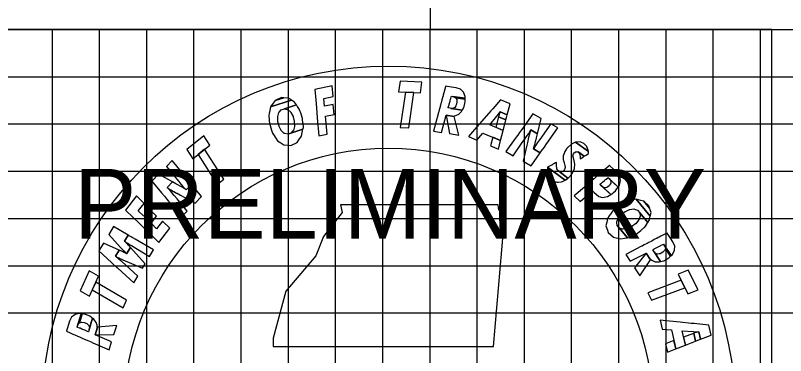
# Model space of a CAD drawing. Extents: x -10 to 342, y -5 to 215.
# Drawn here: x 313.22 to 329.53, y 195.1 to 202.3 of the extents above; entities that cross this region are included whole.
import ezdxf

# ---------------------------------------------------------------- set-up
doc = ezdxf.new("R2010")
doc.units = 0
for name, color, linetype in [('SHEET_LOGO', 7, 'Continuous'), ('SHEET_PRELIM', 7, 'Continuous'), ('SHEET_PROJ_NUMBER', 7, 'Continuous'), ('XS_SHEET_MAJOR_GRIDS', 7, 'Continuous'), ('XS_SHEET_MEDIUM_GRIDS', 7, 'Continuous'), ('XS_SHEET_MINOR_GRIDS', 7, 'Continuous')]:
    doc.layers.add(name, color=color, linetype=linetype)

msp = doc.modelspace()

# ---------------------------------------------------------------- linework, layer by layer
at = {"layer": 'SHEET_LOGO'}
for points in [[(313, 185.757), (329.243, 185.757), (329.243, 202), (313, 202)], [(321.366, 200.903), (321.333, 200.676), (321.797, 200.658), (321.83, 200.885)], [(319.612, 200.131), (319.648, 199.748), (319.82, 199.783), (319.784, 200.165), (319.971, 200.203), (319.952, 200.414), (319.765, 200.376), (319.75, 200.538), (319.95, 200.579), (319.929, 200.804), (319.557, 200.729), (319.578, 200.504), (319.593, 200.342)], [(322.172, 200.213), (322.075, 199.849), (322.247, 199.822), (322.345, 200.185), (322.515, 200.158), (322.512, 200.171), (322.55, 200.178), (322.609, 200.204), (322.67, 200.265), (322.684, 200.291), (322.386, 200.338), (322.388, 200.345), (322.395, 200.371), (322.404, 200.405), (322.408, 200.42), (322.424, 200.48), (322.424, 200.48), (322.436, 200.524), (322.436, 200.524), (322.439, 200.535), (322.449, 200.57), (322.453, 200.586), (322.453, 200.588), (322.743, 200.542), (322.742, 200.584), (322.708, 200.673), (322.644, 200.734), (322.551, 200.765), (322.455, 200.78), (322.331, 200.8), (322.33, 200.8), (322.326, 200.785), (322.313, 200.735), (322.291, 200.655), (322.281, 200.616), (322.28, 200.613), (322.276, 200.598), (322.267, 200.563), (322.264, 200.552), (322.252, 200.508), (322.236, 200.448), (322.231, 200.432), (322.222, 200.399), (322.215, 200.373), (322.213, 200.365), (322.206, 200.339), (322.188, 200.271), (322.179, 200.237), (322.176, 200.225)], [(318.681, 200.44), (318.624, 200.36), (319.064, 200.505), (319.002, 200.546), (318.902, 200.554), (318.719, 200.494)], [(318.853, 200.558), (318.719, 200.494), (318.902, 200.554), (318.854, 200.558)], [(321.48, 200.67), (321.371, 199.923), (321.548, 199.916), (321.656, 200.664)], [(322.485, 200.33), (322.44, 200.329), (322.684, 200.291), (322.687, 200.298), (322.701, 200.323), (322.718, 200.355), (322.721, 200.371), (322.735, 200.431), (322.744, 200.475), (322.744, 200.487), (322.743, 200.524), (322.549, 200.555), (322.567, 200.515), (322.567, 200.503), (322.569, 200.458), (322.553, 200.397), (322.544, 200.383), (322.524, 200.351)], [(322.512, 200.576), (322.549, 200.555), (322.743, 200.524), (322.743, 200.54), (322.743, 200.542), (322.479, 200.584)], [(319.003, 199.55), (319.051, 199.547), (319.185, 199.61), (319.222, 199.662), (319.28, 199.744), (319.295, 199.818), (319.309, 199.886), (318.988, 199.781), (318.987, 199.781), (318.924, 199.796), (318.916, 199.798), (318.914, 199.8), (318.852, 199.857), (318.851, 199.859), (318.849, 199.863), (318.804, 199.946), (318.803, 199.95), (318.802, 199.955), (318.778, 200.043), (318.776, 200.048), (318.776, 200.053), (318.773, 200.149), (318.774, 200.153), (318.774, 200.155), (318.796, 200.239), (318.796, 200.24), (318.804, 200.25), (318.847, 200.301), (318.915, 200.323), (319.169, 200.407), (319.133, 200.459), (319.064, 200.505), (318.624, 200.36), (318.609, 200.287), (318.595, 200.218), (318.595, 200.218), (318.587, 200.178), (318.587, 200.172), (318.587, 200.171), (318.594, 200.095), (318.594, 200.094), (318.595, 200.09), (318.603, 199.996), (318.603, 199.991), (318.604, 199.986), (318.633, 199.899), (318.635, 199.894), (318.636, 199.891), (318.666, 199.802), (318.667, 199.799), (318.669, 199.797), (318.712, 199.734), (318.713, 199.732), (318.715, 199.728), (318.736, 199.698), (318.736, 199.698), (318.771, 199.646), (318.84, 199.599), (318.902, 199.557)], [(319.097, 199.853), (319.055, 199.803), (319.309, 199.887), (319.317, 199.926), (319.317, 199.93), (319.317, 199.932), (319.31, 200.008), (319.31, 200.01), (319.31, 200.01), (319.309, 200.014), (319.301, 200.109), (319.301, 200.113), (319.3, 200.118), (319.271, 200.205), (319.27, 200.21), (319.268, 200.214), (319.239, 200.302), (319.237, 200.305), (319.237, 200.307), (319.194, 200.37), (319.193, 200.371), (319.189, 200.376), (319.169, 200.406), (319.169, 200.407), (318.915, 200.323), (318.916, 200.323), (318.976, 200.306), (318.987, 200.303), (318.988, 200.303), (319.052, 200.246), (319.053, 200.245), (319.054, 200.241), (319.099, 200.159), (319.1, 200.155), (319.102, 200.15), (319.125, 200.061), (319.126, 200.056), (319.126, 200.052), (319.129, 199.954), (319.128, 199.95), (319.127, 199.948), (319.105, 199.863), (319.102, 199.859)], [(322.942, 199.88), (322.813, 199.733), (322.99, 199.659), (323.118, 199.806), (323.496, 199.649), (323.551, 199.862), (323.264, 199.982), (323.414, 200.162), (323.417, 200.165), (323.45, 200.209), (323.451, 200.21), (323.485, 200.257), (323.636, 200.194), (323.696, 200.426), (323.494, 200.51), (323.329, 200.322), (323.29, 200.277), (323.289, 200.276), (323.252, 200.234), (323.249, 200.231), (323.093, 200.053)], [(323.466, 200.202), (323.451, 200.151), (323.608, 200.086), (323.622, 200.138), (323.622, 200.139), (323.636, 200.194), (323.485, 200.257), (323.467, 200.204)], [(323.804, 199.689), (323.608, 199.414), (323.761, 199.327), (323.955, 199.604), (323.955, 199.604), (324.002, 199.672), (324.009, 199.68), (324.047, 199.735), (324.049, 199.738), (324.086, 199.793), (324.092, 199.801), (324.134, 199.872), (324.276, 199.792), (324.354, 200.117), (324.179, 200.216), (323.992, 199.952), (323.944, 199.885), (323.937, 199.876), (323.899, 199.822), (323.897, 199.819), (323.858, 199.765), (323.852, 199.756)], [(322.345, 200.185), (322.412, 199.796), (322.61, 199.764), (322.515, 200.158)], [(323.45, 200.147), (323.392, 199.929), (323.551, 199.862), (323.607, 200.082), (323.608, 200.086), (323.451, 200.151)], [(319.055, 199.803), (318.988, 199.781), (319.309, 199.886), (319.309, 199.887)], [(324.05, 199.55), (323.972, 199.209), (324.14, 199.114), (324.336, 199.389), (324.192, 199.47), (324.217, 199.55), (324.221, 199.561), (324.237, 199.628), (324.238, 199.631), (324.254, 199.698), (324.256, 199.709), (324.276, 199.792), (324.134, 199.872), (324.108, 199.792), (324.105, 199.782), (324.089, 199.715), (324.088, 199.712), (324.072, 199.644), (324.07, 199.634)], [(324.233, 199.541), (324.192, 199.47), (324.336, 199.389), (324.384, 199.456), (324.39, 199.465), (324.429, 199.519), (324.431, 199.522), (324.47, 199.576), (324.476, 199.585), (324.711, 199.916), (324.558, 200.002), (324.323, 199.671), (324.317, 199.662), (324.279, 199.608), (324.277, 199.605), (324.239, 199.55)], [(316.849, 199.457), (316.973, 199.263), (317.336, 199.553), (317.212, 199.746)], [(323.331, 199.718), (323.285, 199.536), (323.449, 199.468), (323.496, 199.649)], [(324.774, 198.979), (324.726, 198.998), (324.923, 198.853), (324.933, 198.862), (324.939, 198.867), (324.955, 198.881), (324.962, 198.89), (324.972, 198.903), (324.994, 198.931), (325.019, 198.963), (325.023, 198.968), (325.034, 198.993), (325.048, 199.025), (325.063, 199.057), (325.064, 199.068), (325.07, 199.139), (325.069, 199.148), (325.056, 199.219), (325.037, 199.282), (325.037, 199.283), (325.029, 199.327), (325.037, 199.366), (325.039, 199.369), (325.06, 199.395), (325.06, 199.395), (325.061, 199.397), (325.065, 199.399), (325.099, 199.416), (325.113, 199.413), (325.113, 199.413), (325.137, 199.409), (325.265, 199.315), (325.307, 199.342), (325.359, 199.375), (325.354, 199.418), (325.085, 199.614), (325.053, 199.599), (324.994, 199.57), (324.959, 199.539), (324.95, 199.532), (324.945, 199.528), (324.92, 199.505), (324.917, 199.502), (324.915, 199.501), (324.896, 199.474), (324.893, 199.471), (324.872, 199.441), (324.855, 199.417), (324.854, 199.416), (324.841, 199.377), (324.823, 199.327), (324.823, 199.319), (324.824, 199.244), (324.828, 199.229), (324.841, 199.177), (324.856, 199.124), (324.861, 199.086), (324.862, 199.078), (324.851, 199.036), (324.828, 199.009), (324.818, 198.996), (324.804, 198.991), (324.782, 198.982)], [(325.118, 199.616), (325.085, 199.614), (325.354, 199.418), (325.351, 199.446), (325.324, 199.513), (325.32, 199.522), (325.26, 199.588), (325.26, 199.588), (325.198, 199.612), (325.178, 199.62)], [(317.087, 199.355), (317.493, 198.718), (317.631, 198.828), (317.225, 199.465)], [(325.181, 199.306), (325.184, 199.264), (325.213, 199.282), (325.216, 199.284), (325.219, 199.286), (325.25, 199.305), (325.255, 199.309), (325.255, 199.309), (325.265, 199.315), (325.137, 199.409), (325.166, 199.375), (325.168, 199.365), (325.18, 199.314), (325.181, 199.309)], [(316.774, 198.666), (316.832, 198.608), (316.949, 198.725), (316.896, 198.79), (316.889, 198.798), (316.847, 198.85), (316.845, 198.852), (316.803, 198.904), (316.796, 198.912), (316.539, 199.226), (316.415, 199.101), (316.673, 198.787), (316.68, 198.779), (316.722, 198.728), (316.724, 198.725), (316.767, 198.675)], [(324.539, 198.85), (324.606, 198.796), (324.619, 198.792), (324.689, 198.766), (324.716, 198.767), (324.786, 198.772), (324.804, 198.78), (324.864, 198.809), (324.491, 199.082), (324.487, 199.012), (324.491, 198.987), (324.501, 198.925), (324.519, 198.89)], [(324.506, 199.09), (324.491, 199.082), (324.864, 198.809), (324.88, 198.817), (324.923, 198.853), (324.726, 198.998), (324.703, 199.031), (324.69, 199.049), (324.685, 199.078), (324.682, 199.095), (324.679, 199.118), (324.679, 199.162), (324.68, 199.187), (324.66, 199.176), (324.626, 199.157), (324.61, 199.148), (324.598, 199.142), (324.579, 199.131), (324.572, 199.127), (324.559, 199.12)], [(325.314, 198.701), (325.055, 198.476), (325.183, 198.357), (325.442, 198.582), (325.476, 198.55), (325.517, 198.512), (325.576, 198.465), (325.657, 198.441), (325.758, 198.464), (325.828, 198.505), (325.6, 198.718), (325.6, 198.719), (325.604, 198.722), (325.621, 198.737), (325.624, 198.739), (325.654, 198.766), (325.696, 198.802), (325.718, 198.821), (325.733, 198.834), (325.758, 198.856), (325.767, 198.864), (325.769, 198.865), (325.984, 198.664), (326.011, 198.703), (326.036, 198.801), (326.021, 198.891), (325.961, 198.969), (325.891, 199.035), (325.799, 199.121), (325.798, 199.121), (325.786, 199.11), (325.744, 199.074), (325.676, 199.015), (325.641, 198.984), (325.639, 198.983), (325.63, 198.975), (325.605, 198.953), (325.59, 198.94), (325.568, 198.921), (325.526, 198.885), (325.496, 198.859), (325.493, 198.856), (325.476, 198.841), (325.472, 198.838), (325.472, 198.838), (325.413, 198.786), (325.348, 198.73), (325.319, 198.705), (325.314, 198.701)], [(316.52, 198.291), (316.734, 198.029), (316.857, 198.154), (316.641, 198.414), (316.641, 198.414), (316.588, 198.478), (316.581, 198.486), (316.539, 198.537), (316.537, 198.54), (316.493, 198.59), (316.487, 198.598), (316.429, 198.657), (316.544, 198.773), (316.25, 198.934), (316.11, 198.791), (316.314, 198.541), (316.367, 198.477), (316.374, 198.469), (316.416, 198.417), (316.418, 198.415), (316.46, 198.363), (316.467, 198.355)], [(316.718, 198.492), (317.027, 198.327), (317.163, 198.464), (316.949, 198.725), (316.832, 198.608), (316.762, 198.653), (316.753, 198.659), (316.692, 198.692), (316.689, 198.694), (316.629, 198.727), (316.619, 198.732), (316.544, 198.773), (316.429, 198.657), (316.499, 198.611), (316.509, 198.605), (316.569, 198.572), (316.572, 198.571), (316.633, 198.538), (316.643, 198.533)], [(325.715, 198.649), (325.675, 198.656), (325.833, 198.508), (325.854, 198.52), (325.857, 198.522), (325.886, 198.55), (325.926, 198.588), (325.947, 198.608), (325.958, 198.625), (325.977, 198.652), (325.983, 198.662), (325.984, 198.664), (325.792, 198.843), (325.814, 198.819), (325.831, 198.788), (325.829, 198.744), (325.819, 198.727), (325.804, 198.701), (325.762, 198.665), (325.719, 198.65)], [(325.641, 198.68), (325.612, 198.707), (325.828, 198.505), (325.829, 198.505), (325.833, 198.508), (325.675, 198.656)], [(316.102, 197.646), (316.259, 197.494), (316.492, 197.793), (316.334, 197.945), (316.209, 197.784), (316.091, 197.898), (316.207, 198.048), (316.053, 198.196), (315.937, 198.046), (315.821, 198.158), (315.946, 198.318), (315.782, 198.476), (315.55, 198.177), (315.713, 198.019), (315.829, 197.907), (315.983, 197.759)], [(325.759, 197.751), (325.775, 197.704), (325.884, 197.604), (325.945, 197.589), (326.043, 197.567), (326.117, 197.58), (326.186, 197.593), (325.967, 197.851), (325.967, 197.851), (325.958, 197.916), (325.957, 197.924), (325.958, 197.927), (325.988, 198.005), (325.989, 198.007), (325.991, 198.01), (326.052, 198.083), (326.055, 198.085), (326.059, 198.088), (326.132, 198.144), (326.136, 198.147), (326.14, 198.149), (326.228, 198.188), (326.232, 198.189), (326.234, 198.189), (326.321, 198.201), (326.321, 198.201), (326.333, 198.197), (326.397, 198.176), (326.443, 198.122), (326.615, 197.918), (326.65, 197.97), (326.667, 198.052), (326.368, 198.405), (326.294, 198.392), (326.225, 198.379), (326.225, 198.379), (326.186, 198.372), (326.18, 198.369), (326.179, 198.368), (326.112, 198.334), (326.11, 198.333), (326.107, 198.331), (326.022, 198.288), (326.018, 198.286), (326.014, 198.284), (325.944, 198.224), (325.94, 198.221), (325.938, 198.218), (325.867, 198.157), (325.864, 198.155), (325.863, 198.153), (325.82, 198.089), (325.819, 198.087), (325.816, 198.083), (325.796, 198.054), (325.796, 198.053), (325.761, 198.001), (325.744, 197.92), (325.728, 197.846)], [(326.464, 198.383), (326.368, 198.405), (326.667, 198.052), (326.682, 198.124), (326.652, 198.22), (326.528, 198.368)], [(323.593, 198.154), (323.458, 198.179), (323.441, 198.289), (320.105, 198.289), (320.139, 198.129), (319.741, 197.621), (319.58, 197.206), (318.945, 196.461), (318.675, 195.47), (318.675, 195.292), (323.348, 195.292)], [(326.638, 198.267), (326.528, 198.368), (326.652, 198.22), (326.638, 198.267)], [(326.076, 197.777), (326.014, 197.797), (326.186, 197.593), (326.225, 197.6), (326.229, 197.602), (326.231, 197.603), (326.299, 197.637), (326.301, 197.638), (326.3, 197.638), (326.304, 197.64), (326.389, 197.684), (326.393, 197.685), (326.398, 197.688), (326.467, 197.748), (326.471, 197.751), (326.474, 197.754), (326.544, 197.814), (326.547, 197.816), (326.548, 197.817), (326.591, 197.881), (326.591, 197.882), (326.595, 197.887), (326.615, 197.918), (326.615, 197.918), (326.443, 198.122), (326.443, 198.121), (326.45, 198.059), (326.451, 198.047), (326.451, 198.046), (326.423, 197.966), (326.422, 197.965), (326.419, 197.962), (326.36, 197.889), (326.356, 197.887), (326.352, 197.884), (326.278, 197.829), (326.274, 197.826), (326.271, 197.824), (326.181, 197.785), (326.177, 197.785), (326.174, 197.785), (326.088, 197.773), (326.083, 197.774)], [(315.558, 197.27), (315.574, 197.255), (315.653, 197.387), (315.639, 197.403), (315.639, 197.403), (315.634, 197.409), (315.632, 197.411), (315.602, 197.444), (315.597, 197.45), (315.597, 197.45), (315.588, 197.461), (315.588, 197.461), (315.586, 197.463), (315.585, 197.464), (315.584, 197.465), (315.584, 197.465), (315.549, 197.5), (315.545, 197.504), (315.529, 197.52), (315.606, 197.648), (315.297, 197.827), (315.197, 197.661), (315.447, 197.384), (315.463, 197.367), (315.466, 197.363), (315.5, 197.326), (315.501, 197.325), (315.502, 197.324), (315.504, 197.322), (315.514, 197.312), (315.519, 197.306), (315.551, 197.276), (315.553, 197.274)], [(326.014, 197.797), (325.967, 197.851), (326.186, 197.593), (326.186, 197.593)], [(315.677, 197.426), (316.061, 197.198), (316.144, 197.336), (315.757, 197.56), (315.739, 197.571), (315.733, 197.574), (315.731, 197.576), (315.731, 197.575), (315.694, 197.597), (315.688, 197.601), (315.676, 197.607), (315.673, 197.609), (315.672, 197.61), (315.671, 197.61), (315.63, 197.635), (315.625, 197.637), (315.606, 197.648), (315.529, 197.52), (315.547, 197.508), (315.551, 197.505), (315.592, 197.478), (315.593, 197.478), (315.594, 197.477), (315.597, 197.475), (315.608, 197.468), (315.614, 197.464), (315.651, 197.442), (315.653, 197.44), (315.659, 197.437)], [(326.481, 197.412), (326.146, 197.239), (326.243, 197.093), (326.577, 197.266), (326.672, 197.122), (326.679, 197.133), (326.71, 197.11), (326.769, 197.084), (326.855, 197.079), (326.883, 197.087), (326.717, 197.338), (326.724, 197.342), (326.748, 197.354), (326.779, 197.37), (326.793, 197.378), (326.848, 197.406), (326.848, 197.406), (326.889, 197.427), (326.888, 197.427), (326.899, 197.432), (326.931, 197.449), (326.945, 197.456), (326.947, 197.457), (327.109, 197.213), (327.139, 197.241), (327.181, 197.327), (327.184, 197.415), (327.144, 197.504), (327.091, 197.586), (327.021, 197.691), (327.021, 197.691), (327.007, 197.684), (326.961, 197.66), (326.887, 197.622), (326.851, 197.603), (326.849, 197.602), (326.835, 197.595), (326.802, 197.578), (326.792, 197.573), (326.752, 197.552), (326.697, 197.523), (326.683, 197.516), (326.652, 197.5), (326.628, 197.488), (326.621, 197.484), (326.597, 197.472), (326.534, 197.439), (326.503, 197.423), (326.492, 197.417)], [(315.387, 196.945), (315.723, 196.636), (315.81, 196.782), (315.472, 197.087), (315.457, 197.101), (315.451, 197.105), (315.451, 197.105), (315.449, 197.107), (315.449, 197.107), (315.416, 197.135), (315.411, 197.14), (315.4, 197.149), (315.398, 197.151), (315.397, 197.152), (315.396, 197.153), (315.358, 197.183), (315.354, 197.186), (315.336, 197.199), (315.415, 197.331), (315.087, 197.479), (314.987, 197.313), (315.256, 197.066), (315.272, 197.05), (315.276, 197.047), (315.312, 197.014), (315.313, 197.013), (315.314, 197.012), (315.317, 197.01), (315.327, 197), (315.332, 196.995), (315.364, 196.965), (315.366, 196.964), (315.371, 196.959)], [(326.978, 197.406), (326.987, 197.364), (327.095, 197.2), (327.107, 197.211), (327.109, 197.213), (326.962, 197.436)], [(315.496, 197.125), (315.909, 196.945), (315.964, 197.037), (315.653, 197.387), (315.574, 197.255), (315.555, 197.264), (315.549, 197.267), (315.547, 197.269), (315.508, 197.288), (315.501, 197.291), (315.489, 197.297), (315.486, 197.298), (315.485, 197.299), (315.484, 197.299), (315.44, 197.319), (315.435, 197.322), (315.415, 197.331), (315.336, 197.199), (315.356, 197.19), (315.361, 197.187), (315.404, 197.167), (315.405, 197.166), (315.407, 197.165), (315.41, 197.164), (315.422, 197.159), (315.429, 197.155), (315.468, 197.138), (315.47, 197.137), (315.477, 197.134)], [(326.577, 197.266), (326.334, 196.954), (326.445, 196.786), (326.672, 197.122)], [(326.778, 197.26), (326.747, 197.293), (326.883, 197.087), (326.891, 197.089), (326.918, 197.096), (326.954, 197.105), (326.967, 197.113), (327.021, 197.144), (327.06, 197.166), (327.069, 197.175), (327.095, 197.2), (326.987, 197.364), (326.97, 197.324), (326.962, 197.316), (326.929, 197.284), (326.874, 197.255), (326.857, 197.252), (326.819, 197.246)], [(314.588, 196.471), (314.786, 196.356), (314.977, 196.779), (314.779, 196.895)], [(327.471, 196.903), (327.256, 196.822), (327.464, 196.407), (327.679, 196.488)], [(314.846, 196.489), (315.499, 196.108), (315.571, 196.269), (314.919, 196.65)], [(327.322, 196.691), (326.615, 196.426), (326.694, 196.268), (327.401, 196.533)], [(314.856, 195.371), (315.202, 195.221), (315.254, 195.387), (314.909, 195.537), (314.96, 195.702), (314.947, 195.7), (314.946, 195.74), (314.929, 195.801), (314.877, 195.871), (314.854, 195.888), (314.764, 195.6), (314.757, 195.603), (314.732, 195.614), (314.7, 195.628), (314.686, 195.634), (314.628, 195.659), (314.628, 195.659), (314.587, 195.677), (314.587, 195.677), (314.576, 195.682), (314.543, 195.696), (314.528, 195.703), (314.526, 195.704), (314.614, 195.983), (314.573, 195.989), (314.48, 195.968), (314.409, 195.914), (314.366, 195.826), (314.336, 195.734), (314.298, 195.613), (314.299, 195.613), (314.313, 195.607), (314.36, 195.587), (314.436, 195.553), (314.474, 195.537), (314.476, 195.536), (314.491, 195.53), (314.524, 195.515), (314.535, 195.511), (314.576, 195.493), (314.633, 195.468), (314.648, 195.461), (314.68, 195.448), (314.704, 195.437), (314.711, 195.434), (314.736, 195.423), (314.801, 195.395), (314.833, 195.381), (314.845, 195.376)], [(314.546, 195.76), (314.573, 195.793), (314.632, 195.981), (314.616, 195.983), (314.614, 195.983), (314.534, 195.728)], [(314.786, 195.697), (314.78, 195.653), (314.854, 195.888), (314.847, 195.893), (314.825, 195.909), (314.795, 195.931), (314.781, 195.937), (314.722, 195.959), (314.68, 195.975), (314.669, 195.976), (314.632, 195.981), (314.573, 195.793), (314.615, 195.806), (314.627, 195.804), (314.672, 195.799), (314.73, 195.774), (314.742, 195.763), (314.771, 195.738)], [(327.07, 195.826), (326.876, 195.845), (326.919, 195.659), (327.113, 195.64), (327.206, 195.241), (327.411, 195.321), (327.341, 195.624), (327.575, 195.606), (327.579, 195.606), (327.634, 195.604), (327.636, 195.604), (327.693, 195.604), (327.73, 195.444), (327.954, 195.531), (327.904, 195.744), (327.655, 195.769), (327.596, 195.775), (327.595, 195.775), (327.539, 195.78), (327.535, 195.781), (327.299, 195.804)], [(314.909, 195.537), (315.304, 195.546), (315.364, 195.738), (314.96, 195.702)], [(327.584, 195.569), (327.372, 195.489), (327.411, 195.321), (327.622, 195.403), (327.626, 195.404), (327.588, 195.57)], [(327.638, 195.588), (327.588, 195.57), (327.626, 195.404), (327.676, 195.423), (327.677, 195.424), (327.73, 195.444), (327.693, 195.604), (327.639, 195.588)], [(327.165, 195.415), (326.991, 195.348), (327.031, 195.174), (327.206, 195.241)]]:
    msp.add_lwpolyline(points, close=True, dxfattribs=at)
for radius in [7.347, 5.608]:
    msp.add_circle((321.121, 193.879), radius, dxfattribs=at)
at = {"layer": 'SHEET_PRELIM'}
msp.add_lwpolyline([(313, 185.757), (329.243, 185.757), (329.243, 202), (313, 202)], close=True, dxfattribs=at)
at = {"layer": 'SHEET_PROJ_NUMBER'}
for p, q in [((322, 210), (322, 202)), ((313, 202), (340, 202))]:
    msp.add_line(p, q, dxfattribs=at)
at = {"layer": 'XS_SHEET_MAJOR_GRIDS'}
for p, q in [((320, 0), (320, 202)), ((5, 200), (340, 200))]:
    msp.add_line(p, q, dxfattribs=at)
at = {"layer": 'XS_SHEET_MEDIUM_GRIDS'}
for p, q in [((315, 0), (315, 202)), ((325, 0), (325, 202))]:
    msp.add_line(p, q, dxfattribs=at)
at = {"layer": 'XS_SHEET_MINOR_GRIDS'}
for p, q in [((314, 0), (314, 202)), ((316, 0), (316, 202)), ((317, 0), (317, 202)), ((318, 0), (318, 202)), ((319, 0), (319, 202)), ((321, 0), (321, 202)), ((322, 0), (322, 202)), ((323, 0), (323, 202)), ((324, 0), (324, 202)), ((326, 0), (326, 202)), ((327, 0), (327, 202)), ((328, 0), (328, 202)), ((329, 0), (329, 202)), ((5, 201), (340, 201)), ((5, 199), (340, 199)), ((5, 198), (340, 198)), ((5, 197), (340, 197)), ((5, 196), (340, 196))]:
    msp.add_line(p, q, dxfattribs=at)

# ---------------------------------------------------------------- texts
at = {"layer": 'SHEET_PRELIM'}
msp.add_text('PRELIMINARY', height=1.47661, dxfattribs=at).set_placement((314.462, 197.57))

doc.saveas('drawing.dxf')
